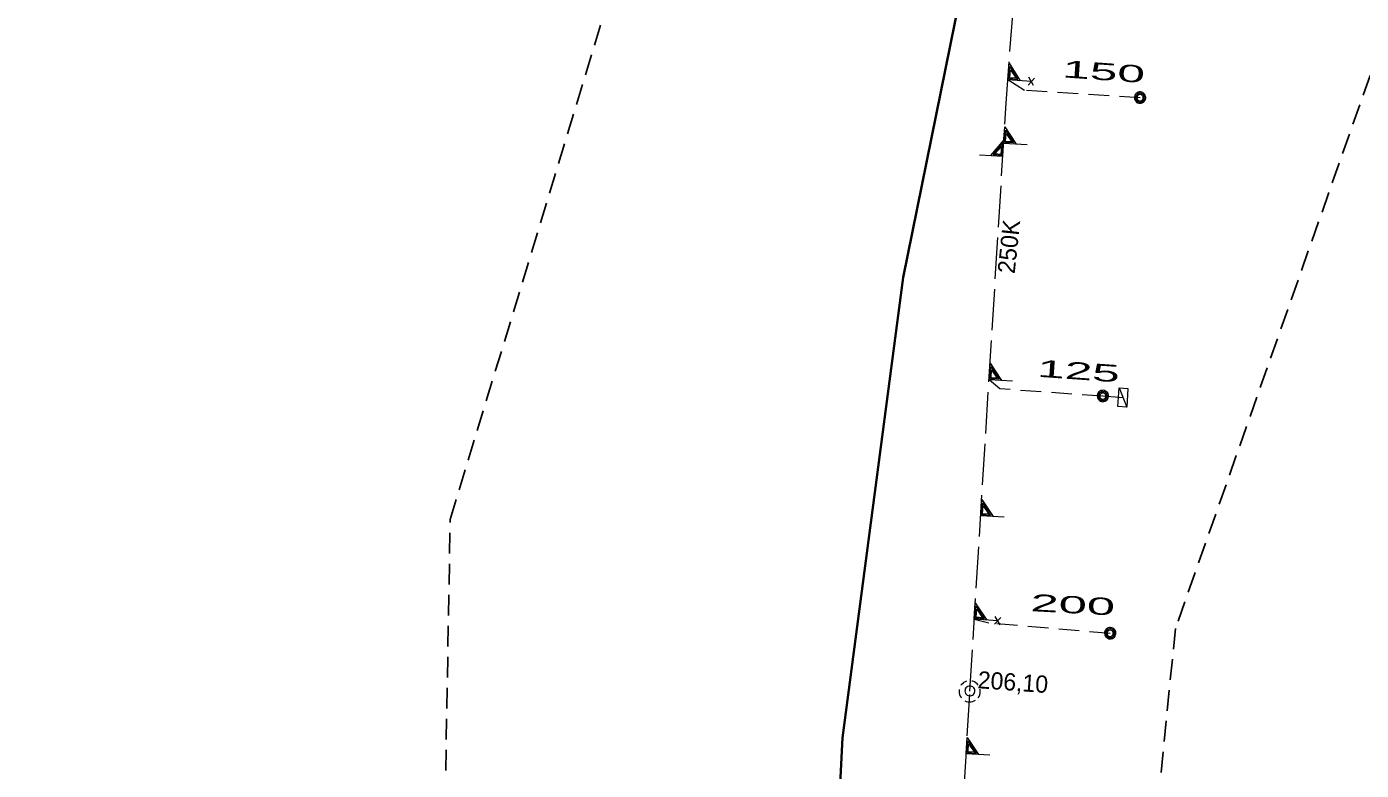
# Model space of a CAD drawing. Extents: x -744446 to -743929, y -1041261 to -1040599.
# Drawn here: x -744445.1 to -744383.1, y -1040870.7 to -1040836.2 of the extents above; entities that cross this region are included whole.
import ezdxf

# ---------------------------------------------------------------- set-up
doc = ezdxf.new("R2010")
doc.units = 0
doc.header["$LTSCALE"] = 0.32
doc.linetypes.add('LONG_DASHED', pattern=[7.5, 6, -1.5])
doc.linetypes.add('MEDIUM_DASHED', pattern=[4.5, 3, -1.5])
for name, color, linetype, lineweight in [('1', 7, 'MEDIUM_DASHED', 25), ('18', 7, 'Continuous', 13), ('20', 7, 'LONG_DASHED', 13), ('49', 7, 'MEDIUM_DASHED', 13)]:
    doc.layers.add(name, color=color, linetype=linetype, lineweight=lineweight)

msp = doc.modelspace()

# ---------------------------------------------------------------- linework, layer by layer
at = {"layer": '1'}
msp.add_lwpolyline([(-744438.077, -1041259.731), (-744438.679, -1041250.888), (-744445.125, -1041198.426), (-744434.434, -1041080.103), (-744426.87, -1040938.41), (-744425.446, -1040859.072), (-744414.192, -1040822.094), (-744390.076, -1040771.45), (-744357.118, -1040726.434), (-744307.278, -1040693.475), (-744241.36, -1040670.967), (-743937.498, -1040598.618), (-743928.655, -1040619.519), (-744129.684, -1040665.585), (-744218.109, -1040687.29), (-744311.358, -1040718.641), (-744361.198, -1040777.323), (-744391.745, -1040864.141), (-744411.355, -1041059.185), (-744416.379, -1041145.154), (-744432.569, -1041193.163), (-744432.047, -1041202.053), (-744422.803, -1041230.992), (-744424.813, -1041260.936)], close=True, dxfattribs=at)
at = {"layer": '18'}
for p, q in [((-744398.302, -1040838.575), (-744398.595, -1040838.889)), ((-744398.339, -1040838.911), (-744398.555, -1040838.523)), ((-744394.363, -1040852.964), (-744394.006, -1040853.862)), ((-744399.862, -1040863.631), (-744400.151, -1040863.949)), ((-744399.895, -1040863.968), (-744400.116, -1040863.582))]:
    msp.add_line(p, q, dxfattribs=at)
for points in [[(-744398.443, -1040838.725), (-744399.535, -1040838.644), (-744399.478, -1040837.877), (-744398.958, -1040838.687)], [(-744399.073, -1040838.628), (-744399.487, -1040838.598), (-744399.445, -1040838.033), (-744399.071, -1040838.629)], [(-744399.152, -1040838.575), (-744399.444, -1040838.554), (-744399.416, -1040838.183), (-744399.153, -1040838.576)], [(-744400.857, -1040842.13), (-744399.763, -1040842.198), (-744399.715, -1040841.428), (-744400.34, -1040842.162)], [(-744398.635, -1040841.67), (-744399.729, -1040841.602), (-744399.682, -1040840.834), (-744399.152, -1040841.638)], [(-744399.267, -1040841.581), (-744399.682, -1040841.555), (-744399.647, -1040840.99), (-744399.266, -1040841.581)], [(-744399.348, -1040841.529), (-744399.638, -1040841.511), (-744399.615, -1040841.14), (-744399.348, -1040841.53)], [(-744400.219, -1040842.118), (-744399.804, -1040842.144), (-744399.769, -1040841.58), (-744400.22, -1040842.118)], [(-744400.132, -1040842.077), (-744399.842, -1040842.095), (-744399.819, -1040841.724), (-744400.132, -1040842.078)], [(-744399.312, -1040852.649), (-744400.406, -1040852.581), (-744400.359, -1040851.813), (-744399.829, -1040852.617)], [(-744399.944, -1040852.56), (-744400.359, -1040852.534), (-744400.324, -1040851.969), (-744399.943, -1040852.56)], [(-744400.025, -1040852.508), (-744400.315, -1040852.49), (-744400.292, -1040852.119), (-744400.025, -1040852.509)], [(-744399.702, -1040858.977), (-744400.796, -1040858.909), (-744400.749, -1040858.141), (-744400.219, -1040858.945)], [(-744400.334, -1040858.888), (-744400.749, -1040858.862), (-744400.714, -1040858.297), (-744400.333, -1040858.888)], [(-744400.415, -1040858.836), (-744400.705, -1040858.818), (-744400.682, -1040858.447), (-744400.415, -1040858.837)], [(-744400.001, -1040863.783), (-744401.094, -1040863.715), (-744401.046, -1040862.947), (-744400.517, -1040863.751)], [(-744400.632, -1040863.694), (-744401.047, -1040863.668), (-744401.012, -1040863.103), (-744400.63, -1040863.694)], [(-744400.712, -1040863.642), (-744401.004, -1040863.624), (-744400.981, -1040863.252), (-744400.712, -1040863.643)], [(-744401.451, -1040866.592), (-744401.522, -1040866.62), (-744401.588, -1040866.659), (-744401.649, -1040866.707), (-744401.7, -1040866.764), (-744401.723, -1040866.798)], [(-744400.909, -1040866.775), (-744400.96, -1040866.717), (-744401.017, -1040866.667), (-744401.083, -1040866.626), (-744401.154, -1040866.597), (-744401.203, -1040866.583)], [(-744401.796, -1040866.984), (-744401.801, -1040867.061), (-744401.796, -1040867.138), (-744401.779, -1040867.213), (-744401.75, -1040867.284), (-744401.71, -1040867.35), (-744401.695, -1040867.372)], [(-744401.538, -1040867.501), (-744401.468, -1040867.532), (-744401.392, -1040867.551), (-744401.316, -1040867.558), (-744401.24, -1040867.553), (-744401.164, -1040867.536), (-744401.093, -1040867.508), (-744401.032, -1040867.473)], [(-744400.914, -1040867.361), (-744400.874, -1040867.296), (-744400.843, -1040867.226), (-744400.823, -1040867.151), (-744400.816, -1040867.075), (-744400.821, -1040866.998), (-744400.826, -1040866.963)], [(-744400.374, -1040870.033), (-744401.468, -1040869.969), (-744401.423, -1040869.201), (-744400.891, -1040870.003)], [(-744401.006, -1040869.946), (-744401.421, -1040869.922), (-744401.388, -1040869.357), (-744401.005, -1040869.946)], [(-744401.087, -1040869.895), (-744401.378, -1040869.878), (-744401.356, -1040869.506), (-744401.087, -1040869.896)]]:
    msp.add_lwpolyline(points, dxfattribs=at)
for points in [[(-744393.128, -1040839.474), (-744393.134, -1040839.418), (-744393.151, -1040839.365), (-744393.179, -1040839.316), (-744393.218, -1040839.275), (-744393.264, -1040839.243), (-744393.316, -1040839.221), (-744393.371, -1040839.21), (-744393.427, -1040839.212), (-744393.482, -1040839.225), (-744393.532, -1040839.25), (-744393.577, -1040839.285), (-744393.613, -1040839.328), (-744393.638, -1040839.378), (-744393.653, -1040839.433), (-744393.656, -1040839.489), (-744393.647, -1040839.544), (-744393.626, -1040839.597), (-744393.595, -1040839.643), (-744393.554, -1040839.682), (-744393.507, -1040839.712), (-744393.454, -1040839.731), (-744393.398, -1040839.738), (-744393.342, -1040839.734), (-744393.288, -1040839.717), (-744393.239, -1040839.69), (-744393.197, -1040839.652), (-744393.164, -1040839.607), (-744393.141, -1040839.556), (-744393.129, -1040839.501)], [(-744393.187, -1040839.477), (-744393.193, -1040839.428), (-744393.211, -1040839.382), (-744393.239, -1040839.341), (-744393.276, -1040839.308), (-744393.32, -1040839.286), (-744393.368, -1040839.274), (-744393.417, -1040839.274), (-744393.465, -1040839.286), (-744393.509, -1040839.309), (-744393.546, -1040839.342), (-744393.574, -1040839.383), (-744393.591, -1040839.43), (-744393.597, -1040839.479), (-744393.59, -1040839.528), (-744393.572, -1040839.574), (-744393.544, -1040839.614), (-744393.507, -1040839.647), (-744393.463, -1040839.669), (-744393.414, -1040839.681), (-744393.365, -1040839.68), (-744393.317, -1040839.668), (-744393.274, -1040839.644), (-744393.237, -1040839.611), (-744393.209, -1040839.57), (-744393.193, -1040839.523)], [(-744393.246, -1040839.481), (-744393.252, -1040839.439), (-744393.269, -1040839.401), (-744393.297, -1040839.37), (-744393.331, -1040839.347), (-744393.372, -1040839.336), (-744393.414, -1040839.336), (-744393.454, -1040839.348), (-744393.489, -1040839.371), (-744393.516, -1040839.403), (-744393.532, -1040839.441), (-744393.538, -1040839.482), (-744393.532, -1040839.524), (-744393.514, -1040839.561), (-744393.486, -1040839.593), (-744393.45, -1040839.615), (-744393.41, -1040839.626), (-744393.368, -1040839.625), (-744393.328, -1040839.612), (-744393.294, -1040839.589), (-744393.267, -1040839.556), (-744393.251, -1040839.518)], [(-744394.856, -1040853.339), (-744394.862, -1040853.283), (-744394.879, -1040853.23), (-744394.907, -1040853.181), (-744394.946, -1040853.14), (-744394.992, -1040853.108), (-744395.044, -1040853.086), (-744395.099, -1040853.075), (-744395.155, -1040853.077), (-744395.21, -1040853.09), (-744395.261, -1040853.115), (-744395.305, -1040853.15), (-744395.341, -1040853.193), (-744395.366, -1040853.243), (-744395.381, -1040853.298), (-744395.384, -1040853.354), (-744395.375, -1040853.409), (-744395.354, -1040853.462), (-744395.323, -1040853.508), (-744395.282, -1040853.547), (-744395.235, -1040853.577), (-744395.182, -1040853.596), (-744395.126, -1040853.603), (-744395.07, -1040853.599), (-744395.016, -1040853.582), (-744394.967, -1040853.555), (-744394.925, -1040853.517), (-744394.892, -1040853.472), (-744394.869, -1040853.421), (-744394.857, -1040853.366)], [(-744394.915, -1040853.342), (-744394.921, -1040853.293), (-744394.939, -1040853.247), (-744394.967, -1040853.206), (-744395.004, -1040853.173), (-744395.048, -1040853.151), (-744395.096, -1040853.139), (-744395.145, -1040853.139), (-744395.193, -1040853.151), (-744395.237, -1040853.174), (-744395.274, -1040853.207), (-744395.302, -1040853.248), (-744395.319, -1040853.295), (-744395.325, -1040853.344), (-744395.318, -1040853.393), (-744395.3, -1040853.439), (-744395.272, -1040853.479), (-744395.235, -1040853.512), (-744395.191, -1040853.534), (-744395.142, -1040853.546), (-744395.093, -1040853.545), (-744395.045, -1040853.533), (-744395.002, -1040853.509), (-744394.965, -1040853.476), (-744394.937, -1040853.435), (-744394.921, -1040853.388)], [(-744394.974, -1040853.346), (-744394.98, -1040853.304), (-744394.997, -1040853.266), (-744395.025, -1040853.235), (-744395.059, -1040853.212), (-744395.1, -1040853.201), (-744395.142, -1040853.201), (-744395.182, -1040853.213), (-744395.217, -1040853.236), (-744395.244, -1040853.268), (-744395.261, -1040853.306), (-744395.266, -1040853.347), (-744395.26, -1040853.389), (-744395.242, -1040853.426), (-744395.214, -1040853.458), (-744395.178, -1040853.48), (-744395.138, -1040853.491), (-744395.096, -1040853.49), (-744395.056, -1040853.477), (-744395.022, -1040853.454), (-744394.995, -1040853.421), (-744394.979, -1040853.383)], [(-744393.952, -1040852.986), (-744394.006, -1040853.858), (-744394.417, -1040853.833), (-744394.363, -1040852.96)], [(-744394.516, -1040864.361), (-744394.522, -1040864.305), (-744394.539, -1040864.252), (-744394.568, -1040864.203), (-744394.606, -1040864.162), (-744394.652, -1040864.13), (-744394.704, -1040864.108), (-744394.759, -1040864.097), (-744394.815, -1040864.099), (-744394.87, -1040864.112), (-744394.921, -1040864.137), (-744394.965, -1040864.172), (-744395.001, -1040864.215), (-744395.026, -1040864.265), (-744395.041, -1040864.32), (-744395.044, -1040864.376), (-744395.035, -1040864.431), (-744395.014, -1040864.484), (-744394.983, -1040864.53), (-744394.943, -1040864.569), (-744394.895, -1040864.599), (-744394.842, -1040864.618), (-744394.786, -1040864.625), (-744394.73, -1040864.621), (-744394.676, -1040864.604), (-744394.627, -1040864.577), (-744394.585, -1040864.539), (-744394.552, -1040864.494), (-744394.529, -1040864.443), (-744394.517, -1040864.388)], [(-744394.575, -1040864.364), (-744394.581, -1040864.315), (-744394.599, -1040864.269), (-744394.627, -1040864.228), (-744394.664, -1040864.195), (-744394.708, -1040864.173), (-744394.756, -1040864.161), (-744394.805, -1040864.161), (-744394.853, -1040864.173), (-744394.897, -1040864.196), (-744394.934, -1040864.229), (-744394.962, -1040864.27), (-744394.979, -1040864.317), (-744394.985, -1040864.366), (-744394.978, -1040864.415), (-744394.96, -1040864.461), (-744394.932, -1040864.501), (-744394.895, -1040864.534), (-744394.851, -1040864.556), (-744394.802, -1040864.568), (-744394.753, -1040864.567), (-744394.705, -1040864.555), (-744394.662, -1040864.531), (-744394.625, -1040864.498), (-744394.597, -1040864.457), (-744394.581, -1040864.41)], [(-744394.634, -1040864.368), (-744394.64, -1040864.326), (-744394.657, -1040864.288), (-744394.685, -1040864.257), (-744394.72, -1040864.234), (-744394.76, -1040864.223), (-744394.802, -1040864.223), (-744394.842, -1040864.235), (-744394.877, -1040864.258), (-744394.904, -1040864.29), (-744394.921, -1040864.328), (-744394.926, -1040864.369), (-744394.92, -1040864.411), (-744394.902, -1040864.448), (-744394.874, -1040864.48), (-744394.838, -1040864.502), (-744394.798, -1040864.513), (-744394.756, -1040864.512), (-744394.716, -1040864.499), (-744394.682, -1040864.476), (-744394.655, -1040864.443), (-744394.639, -1040864.405)], [(-744401.066, -1040867.044), (-744401.073, -1040866.992), (-744401.09, -1040866.942), (-744401.119, -1040866.898), (-744401.157, -1040866.861), (-744401.201, -1040866.834), (-744401.252, -1040866.818), (-744401.304, -1040866.813), (-744401.355, -1040866.82), (-744401.404, -1040866.839), (-744401.448, -1040866.869), (-744401.483, -1040866.908), (-744401.51, -1040866.953), (-744401.524, -1040867.004), (-744401.527, -1040867.056), (-744401.519, -1040867.108), (-744401.499, -1040867.156), (-744401.468, -1040867.199), (-744401.429, -1040867.234), (-744401.382, -1040867.258), (-744401.331, -1040867.272), (-744401.279, -1040867.274), (-744401.228, -1040867.264), (-744401.179, -1040867.242), (-744401.137, -1040867.21), (-744401.105, -1040867.17), (-744401.081, -1040867.123), (-744401.068, -1040867.072)]]:
    msp.add_lwpolyline(points, close=True, dxfattribs=at)
at = {"layer": '20'}
msp.add_line((-744404.072, -1040914.656), (-744401.298, -1040867.055), dxfattribs=at)
at = {"layer": '20', "linetype": 'Continuous', "lineweight": 35}
msp.add_lwpolyline([(-744429.62, -1041252.21), (-744428.789, -1041237.94), (-744437.959, -1041195.193), (-744423.3, -1041145.69), (-744417.879, -1041053.98), (-744409.949, -1040917.67), (-744407.76, -1040880.01), (-744407.219, -1040869.23), (-744404.395, -1040847.829), (-744400.25, -1040827.35), (-744393.491, -1040807.621), (-744384.879, -1040787.9), (-744372.238, -1040768.547), (-744361.26, -1040752.62), (-744345.317, -1040736.555), (-744330.739, -1040723.14), (-744312.333, -1040710.859), (-744294.67, -1040700.75), (-744274.728, -1040692.583), (-744254.699, -1040686.49), (-744133.87, -1040657.39), (-743953.289, -1040613.85), (-743946.017, -1040612.141)], dxfattribs=at)
at = {"layer": '20'}
msp.add_lwpolyline([(-744401.298, -1040867.055), (-744399.614, -1040839.73), (-744397.87, -1040816.172)], dxfattribs=at)
at = {"layer": '49'}
msp.add_line((-744394.181, -1040853.419), (-744395.12, -1040853.352), dxfattribs=at)
for points in [[(-744393.392, -1040839.487), (-744398.756, -1040839.142), (-744399.534, -1040838.65)], [(-744395.12, -1040853.352), (-744399.901, -1040853.008), (-744400.406, -1040852.582)], [(-744394.78, -1040864.374), (-744400.418, -1040863.894), (-744401.093, -1040863.721)]]:
    msp.add_lwpolyline(points, dxfattribs=at)

# ---------------------------------------------------------------- texts
at = {"layer": '1'}
for s, rotation, width, p in [('150 ', 356, 2.15, (-744397.021, -1040838.528)), ('125 ', 356, 2.15, (-744398.189, -1040852.441)), ('200 ', 357, 2.2, (-744398.497, -1040863.335))]:
    msp.add_text(s, height=0.8, rotation=rotation, dxfattribs=dict(at, width=width)).set_placement(p)
for s, rotation, p in [('250K', 84, (-744399.219, -1040847.68)), ('206,10', 356, (-744400.956, -1040866.917))]:
    msp.add_text(s, height=0.8, rotation=rotation, dxfattribs=at).set_placement(p)

doc.saveas('drawing.dxf')
